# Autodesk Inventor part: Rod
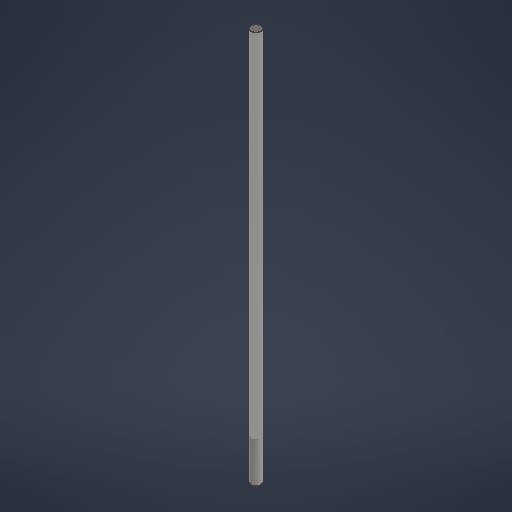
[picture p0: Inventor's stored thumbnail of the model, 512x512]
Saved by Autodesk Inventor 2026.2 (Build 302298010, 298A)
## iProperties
Created: 2026-05
Part Number: Rod
Material: 스테인리스스틸
Document SubType Name: Modeling
Designer: work
Density: 8 g/cm^3
Appearance: 반연마
Author: work
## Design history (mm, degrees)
sketch "스케치1"
  geometry: C1 r 2 at (0, 0); 1 further point
  constraints: 1 centre point, 1 coincident
  dimensions: "d0" = 4 diameter of C1
extrude "돌출1" new body sketch "스케치1" distance "d1" = 160; taper "d2" = 0 deg
feature "스레드1" dims "d3" = 17, "d4" = 0
chamfer "모따기1" distance "d5" = 0.5; stored, may be unused: second distance "d6" = 2, angle "d7" = 45 deg
node "솔리드1"
feature "A9D066F2-1C7D-4E18-AEED-F7BC21143FA4" dims "d3" = 17, "d4" = 0
